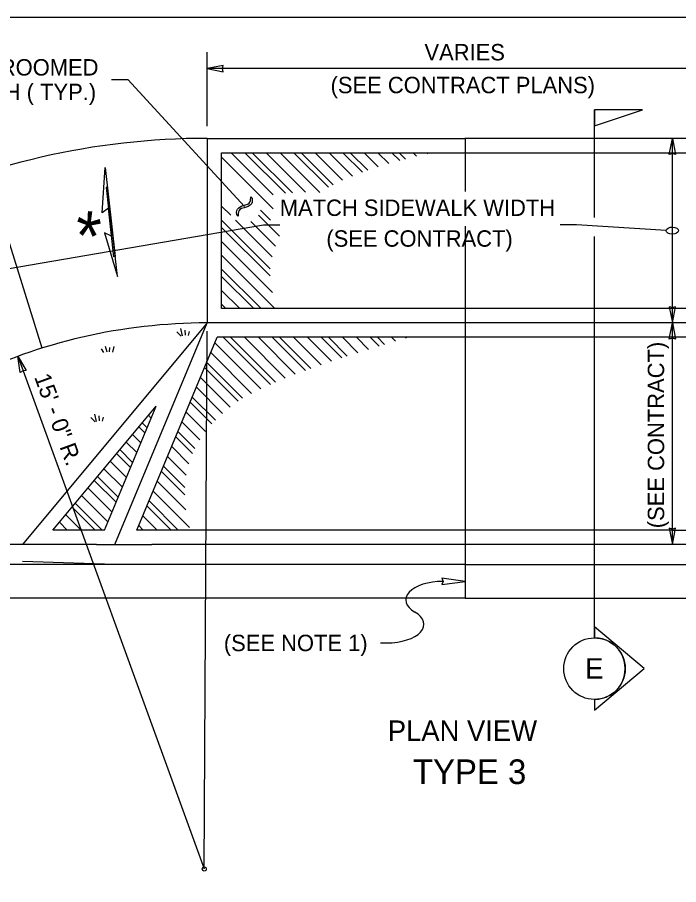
# Model space of a CAD drawing. Extents: x 99862 to 103151, y 100000 to 105076.
# Drawn here: x 100381 to 101026, y 104230 to 105076 of the extents above; entities that cross this region are included whole.
import ezdxf

# ---------------------------------------------------------------- set-up
doc = ezdxf.new("R2010")
doc.units = 0
for name, color, linetype in [('Level 1', 7, 'Continuous'), ('Level 15', 7, 'Continuous'), ('Level 18', 7, 'Continuous'), ('Level 20', 7, 'Continuous'), ('Level 48', 7, 'Continuous'), ('Level 50', 7, 'Continuous'), ('Level 57', 7, 'Continuous'), ('Level 58', 7, 'Continuous'), ('Level 7', 7, 'Continuous'), ('Level 9', 7, 'Continuous')]:
    doc.layers.add(name, color=color, linetype=linetype)

msp = doc.modelspace()

# ---------------------------------------------------------------- linework, layer by layer
at = {"layer": 'Level 1'}
msp.add_lwpolyline([(99862, 102999.5), (103151, 102999.5), (103151, 105075.5), (99862, 105075.5)], close=True, dxfattribs=at)
at = {"layer": 'Level 15'}
for p, q in [((100565.71, 104969.5), (100565.71, 105041.5)), ((100565.71, 104969.5), (100565.71, 105041.5)), ((100472.34, 105014.76), (100488.34, 105014.76)), ((100472.34, 105014.76), (100488.34, 105014.76)), ((100602.22, 104891.13), (100488.34, 105014.76)), ((100602.22, 104891.13), (100488.34, 105014.76)), ((101019.71, 104777.5), (101019.71, 104957.5)), ((100342.07, 104825.3), (100620.7, 104873.16)), ((100620.7, 104873.16), (100636.7, 104873.16)), ((100926.15, 104873.16), (100910.15, 104873.16)), ((101013.72, 104867.6), (100926.15, 104873.16)), ((101019.71, 104561.5), (101019.71, 104777.5)), ((101019.71, 104561.5), (101019.71, 104777.5)), ((100735.07, 104465.44), (100741.07, 104465.44)), ((100735.07, 104465.44), (100741.07, 104465.44))]:
    msp.add_line(p, q, dxfattribs=at)
for points in [[(100565.71, 105025.5), (100581.44, 105022.42), (100580.71, 105025.5), (100581.44, 105028.59)], [(100565.71, 105025.5), (100581.44, 105022.42), (100580.71, 105025.5), (100581.44, 105028.59)], [(101019.71, 104957.5), (101022.8, 104941.78), (101019.71, 104942.51), (101016.63, 104941.78)], [(101019.71, 104957.5), (101022.8, 104941.78), (101019.71, 104942.51), (101016.63, 104941.78)], [(101019.71, 104777.5), (101022.8, 104793.23), (101019.71, 104792.5), (101016.63, 104793.23)], [(101019.71, 104777.5), (101022.8, 104793.23), (101019.71, 104792.5), (101016.63, 104793.23)], [(101019.71, 104777.5), (101022.8, 104761.78), (101019.71, 104762.51), (101016.63, 104761.78)], [(101019.71, 104777.5), (101022.8, 104761.78), (101019.71, 104762.51), (101016.63, 104761.78)], [(100381.04, 104744.94), (100389.32, 104731.22), (100386.17, 104730.85), (100383.52, 104729.11)], [(100381.04, 104744.94), (100389.32, 104731.22), (100386.17, 104730.85), (100383.52, 104729.11)], [(101019.71, 104561.5), (101022.8, 104577.23), (101019.71, 104576.5), (101016.63, 104577.23)], [(101019.71, 104561.5), (101022.8, 104577.23), (101019.71, 104576.5), (101016.63, 104577.23)], [(100817.72, 104525.5), (100794.89, 104528.49), (100795.95, 104525.5), (100794.89, 104522.51)], [(100817.72, 104525.5), (100794.89, 104528.49), (100795.95, 104525.5), (100794.89, 104522.51)]]:
    msp.add_lwpolyline(points, close=True, dxfattribs=at)
msp.add_lwpolyline([(101069.71, 105025.5), (100565.71, 105025.5)], dxfattribs=at)
msp.add_lwpolyline([(101069.71, 105025.5), (100565.71, 105025.5)], dxfattribs=at)
msp.add_circle((100562.98, 104245.01), 2, dxfattribs=at)
msp.add_circle((100562.98, 104245.01), 2, dxfattribs=at)
msp.add_ellipse((101019.71, 104867.5), major_axis=(-6, 0.1), ratio=0.57735, dxfattribs=at)
msp.add_ellipse((101019.71, 104867.5), major_axis=(-6, 0.1), ratio=0.57735, dxfattribs=at)
for centre, start_param, end_param in [((100795.95, 104507.35), 4.712389, 6.99691), ((100795.95, 104507.35), 4.712389, 6.99691), ((100741.07, 104483.59), 1.570796, 3.855317), ((100741.07, 104483.59), 1.570796, 3.855317)]:
    msp.add_ellipse(centre, major_axis=(-36.3, 0), ratio=0.5, start_param=start_param, end_param=end_param, dxfattribs=at)
at = {"layer": 'Level 18'}
for p, q in [((100540.36, 104764.54), (100536.09, 104768.8)), ((100540.36, 104764.54), (100536.09, 104768.8)), ((100541.78, 104764.89), (100540, 104772)), ((100541.78, 104764.89), (100540, 104772)), ((100544.62, 104765.6), (100544.27, 104770.58)), ((100544.62, 104765.6), (100544.27, 104770.58)), ((100547.46, 104765.25), (100548.53, 104769.16)), ((100547.46, 104765.25), (100548.53, 104769.16)), ((100462.38, 104752.2), (100464.76, 104748.64)), ((100462.38, 104752.2), (100464.76, 104748.64)), ((100466.34, 104754.98), (100467.93, 104749.43)), ((100466.34, 104754.98), (100467.93, 104749.43)), ((100470.7, 104753.39), (100470.3, 104749.43)), ((100470.7, 104753.39), (100470.3, 104749.43)), ((100474.65, 104754.58), (100473.47, 104749.04)), ((100474.65, 104754.58), (100473.47, 104749.04)), ((100457.9, 104681.32), (100456.12, 104688.43)), ((100457.9, 104681.32), (100456.12, 104688.43)), ((100456.47, 104680.96), (100452.21, 104685.23)), ((100456.47, 104680.96), (100452.21, 104685.23)), ((100460.74, 104682.03), (100460.38, 104687.01)), ((100460.74, 104682.03), (100460.38, 104687.01)), ((100463.58, 104681.67), (100464.65, 104685.58)), ((100463.58, 104681.67), (100464.65, 104685.58))]:
    msp.add_line(p, q, dxfattribs=at)
at = {"layer": 'Level 20'}
for p, q in [((100608.14, 104896.88), (100608.33, 104900.58)), ((100608.14, 104896.88), (100608.33, 104900.58)), ((100608.33, 104900.58), (100609.76, 104899.01)), ((100608.33, 104900.58), (100609.76, 104899.01)), ((100596.64, 104889.9), (100598.94, 104891.36)), ((100596.64, 104889.9), (100598.94, 104891.36)), ((100598.94, 104891.36), (100603.15, 104892.66)), ((100598.94, 104891.36), (100603.15, 104892.66)), ((100603.15, 104892.66), (100605.47, 104893.38)), ((100603.15, 104892.66), (100605.47, 104893.38)), ((100605.47, 104893.38), (100606.72, 104894.2)), ((100605.47, 104893.38), (100606.72, 104894.2)), ((100607.85, 104892.37), (100605.8, 104891)), ((100607.85, 104892.37), (100605.8, 104891)), ((100606.72, 104894.2), (100607.59, 104895.33)), ((100606.72, 104894.2), (100607.59, 104895.33)), ((100607.59, 104895.33), (100608.14, 104896.88)), ((100607.59, 104895.33), (100608.14, 104896.88)), ((100608.93, 104893.63), (100607.85, 104892.37)), ((100608.93, 104893.63), (100607.85, 104892.37)), ((100609.59, 104895.11), (100608.93, 104893.63)), ((100609.59, 104895.11), (100608.93, 104893.63)), ((100609.86, 104896.87), (100609.59, 104895.11)), ((100609.86, 104896.87), (100609.59, 104895.11)), ((100609.76, 104899.01), (100609.86, 104896.87)), ((100609.76, 104899.01), (100609.86, 104896.87)), ((100594.55, 104885.23), (100594.8, 104887)), ((100594.55, 104885.23), (100594.8, 104887)), ((100594.72, 104883.24), (100594.55, 104885.23)), ((100594.72, 104883.24), (100594.55, 104885.23)), ((100596.14, 104881.68), (100594.72, 104883.24)), ((100596.14, 104881.68), (100594.72, 104883.24)), ((100594.8, 104887), (100595.5, 104888.55)), ((100594.8, 104887), (100595.5, 104888.55)), ((100595.5, 104888.55), (100596.64, 104889.9)), ((100595.5, 104888.55), (100596.64, 104889.9)), ((100596.4, 104885.82), (100596.14, 104884.11)), ((100596.4, 104885.82), (100596.14, 104884.11)), ((100596.14, 104884.11), (100596.15, 104881.68)), ((100596.14, 104884.11), (100596.15, 104881.68)), ((100596.95, 104887.07), (100596.4, 104885.82)), ((100596.95, 104887.07), (100596.4, 104885.82)), ((100597.8, 104888.1), (100596.95, 104887.07)), ((100597.8, 104888.1), (100596.95, 104887.07)), ((100599.43, 104889.1), (100597.8, 104888.1)), ((100599.43, 104889.1), (100597.8, 104888.1)), ((100601.87, 104889.87), (100599.43, 104889.1)), ((100601.87, 104889.87), (100599.43, 104889.1)), ((100605.8, 104891), (100601.87, 104889.87)), ((100605.8, 104891), (100601.87, 104889.87))]:
    msp.add_line(p, q, dxfattribs=at)
for points in [[(100474.84, 104842.11), (100469.46, 104889.29), (100463.45, 104884.85), (100466.16, 104929.19), (100476.07, 104842.25)], [(100467.25, 104909.43), (100472.62, 104862.25), (100465.76, 104865.23), (100478.38, 104822.64), (100468.48, 104909.57)], [(100467.25, 104909.43), (100472.62, 104862.25), (100465.76, 104865.23), (100478.38, 104822.64), (100468.48, 104909.57)], [(100467.25, 104909.43), (100472.62, 104862.25), (100465.76, 104865.23), (100478.38, 104822.64), (100468.48, 104909.57)], [(100467.25, 104909.43), (100472.62, 104862.25), (100465.76, 104865.23), (100478.38, 104822.64), (100468.48, 104909.57)]]:
    msp.add_lwpolyline(points, close=True, dxfattribs=at)
at = {"layer": 'Level 48'}
for p, q in [((100579.94, 104943.5), (101055.71, 104943.5)), ((100579.94, 104791.5), (100579.94, 104943.5)), ((100579.94, 104943.5), (101055.71, 104943.5)), ((100579.94, 104791.5), (100579.94, 104943.5)), ((101055.71, 104791.5), (100579.94, 104791.5)), ((101055.71, 104791.5), (100579.94, 104791.5)), ((100497.28, 104575.5), (100575.61, 104763.5)), ((100497.28, 104575.5), (100575.61, 104763.5)), ((101059.94, 104763.5), (100575.61, 104763.5)), ((101059.94, 104763.5), (100575.61, 104763.5)), ((100415.28, 104575.5), (100516.03, 104696.4)), ((100415.28, 104575.5), (100516.03, 104696.4)), ((100465.66, 104575.5), (100516.03, 104696.4)), ((100465.66, 104575.5), (100516.03, 104696.4)), ((100465.66, 104575.5), (100415.28, 104575.5)), ((100465.66, 104575.5), (100415.28, 104575.5)), ((101020.48, 104575.5), (100497.28, 104575.5)), ((101020.48, 104575.5), (100497.28, 104575.5)), ((101020.48, 104575.5), (101138.27, 104575.5)), ((101020.48, 104575.5), (101138.27, 104575.5))]:
    msp.add_line(p, q, dxfattribs=at)
at = {"layer": 'Level 50'}
for p, q in [((100589.11, 104943.5), (100630.08, 104902.53)), ((100602.69, 104943.5), (100642.15, 104904.04)), ((100609.76, 104943.5), (100649.01, 104904.25)), ((100623.34, 104943.5), (100661.86, 104904.98)), ((100636.91, 104943.5), (100675.61, 104904.8)), ((100650.49, 104943.5), (100684.21, 104909.78)), ((100650.49, 104943.5), (100684.21, 104909.78)), ((100657.56, 104943.5), (100688.84, 104912.22)), ((100657.56, 104943.5), (100688.84, 104912.22)), ((100671.14, 104943.5), (100698.02, 104916.62)), ((100671.14, 104943.5), (100698.02, 104916.62)), ((100684.71, 104943.5), (100707.52, 104920.7)), ((100684.71, 104943.5), (100707.52, 104920.7)), ((100698.29, 104943.5), (100717.31, 104924.48)), ((100698.29, 104943.5), (100717.31, 104924.48)), ((100705.36, 104943.5), (100722.51, 104926.35)), ((100705.36, 104943.5), (100722.51, 104926.35)), ((100718.94, 104943.5), (100732.69, 104929.75)), ((100718.94, 104943.5), (100732.69, 104929.75)), ((100732.51, 104943.5), (100743.1, 104932.92)), ((100732.51, 104943.5), (100743.1, 104932.92)), ((100746.09, 104943.5), (100753.71, 104935.88)), ((100746.09, 104943.5), (100753.71, 104935.88)), ((100753.16, 104943.5), (100759.31, 104937.35)), ((100753.16, 104943.5), (100759.31, 104937.35)), ((100766.74, 104943.5), (100770.21, 104940.03)), ((100766.74, 104943.5), (100770.21, 104940.03)), ((100780.31, 104943.5), (100781.27, 104942.55)), ((100780.31, 104943.5), (100781.27, 104942.55)), ((100579.94, 104939.09), (100630.13, 104888.91)), ((100579.94, 104891.29), (100588.77, 104882.47)), ((100579.94, 104891.29), (100588.77, 104882.47)), ((100615.77, 104882.62), (100636.42, 104861.97)), ((100615.77, 104882.62), (100636.42, 104861.97)), ((100617.83, 104887.63), (100627.62, 104877.84)), ((100579.94, 104877.72), (100627.39, 104830.27)), ((100579.94, 104877.72), (100627.39, 104830.27)), ((100593.55, 104877.68), (100629.22, 104842.02)), ((100593.55, 104877.68), (100629.22, 104842.02)), ((100608.43, 104876.39), (100632.37, 104852.44)), ((100608.43, 104876.39), (100632.37, 104852.44)), ((100579.94, 104870.65), (100627.23, 104823.36)), ((100579.94, 104870.65), (100627.23, 104823.36)), ((100579.94, 104857.07), (100629.7, 104807.31)), ((100579.94, 104857.07), (100629.7, 104807.31)), ((100579.94, 104843.49), (100631.93, 104791.5)), ((100579.94, 104843.49), (100631.93, 104791.5)), ((100579.94, 104829.92), (100618.36, 104791.5)), ((100579.94, 104829.92), (100618.36, 104791.5)), ((100579.94, 104822.85), (100611.29, 104791.5)), ((100579.94, 104822.85), (100611.29, 104791.5)), ((100579.94, 104809.27), (100597.71, 104791.5)), ((100579.94, 104809.27), (100597.71, 104791.5)), ((100579.94, 104795.69), (100584.13, 104791.5)), ((100579.94, 104795.69), (100584.13, 104791.5)), ((100573.38, 104758.13), (100618.15, 104713.36)), ((100573.38, 104758.13), (100618.15, 104713.36)), ((100581.59, 104763.5), (100627.48, 104717.6)), ((100581.59, 104763.5), (100627.48, 104717.6)), ((100588.66, 104763.5), (100632.43, 104719.73)), ((100588.66, 104763.5), (100632.43, 104719.73)), ((100602.23, 104763.5), (100642.05, 104723.69)), ((100602.23, 104763.5), (100642.05, 104723.69)), ((100615.81, 104763.5), (100651.81, 104727.5)), ((100615.81, 104763.5), (100651.81, 104727.5)), ((100629.39, 104763.5), (100661.7, 104731.19)), ((100629.39, 104763.5), (100661.7, 104731.19)), ((100636.46, 104763.5), (100666.89, 104733.07)), ((100636.46, 104763.5), (100666.89, 104733.07)), ((100650.03, 104763.5), (100676.92, 104736.61)), ((100650.03, 104763.5), (100676.92, 104736.61)), ((100663.61, 104763.5), (100687.04, 104740.07)), ((100663.61, 104763.5), (100687.04, 104740.07)), ((100677.19, 104763.5), (100697.23, 104743.46)), ((100677.19, 104763.5), (100697.23, 104743.46)), ((100684.26, 104763.5), (100702.56, 104745.2)), ((100684.26, 104763.5), (100702.56, 104745.2)), ((100697.83, 104763.5), (100712.84, 104748.49)), ((100697.83, 104763.5), (100712.84, 104748.49)), ((100711.41, 104763.5), (100723.18, 104751.73)), ((100711.41, 104763.5), (100723.18, 104751.73)), ((100724.99, 104763.5), (100733.57, 104754.92)), ((100724.99, 104763.5), (100733.57, 104754.92)), ((100732.06, 104763.5), (100739, 104756.56)), ((100732.06, 104763.5), (100739, 104756.56)), ((100745.63, 104763.5), (100749.46, 104759.68)), ((100745.63, 104763.5), (100749.46, 104759.68)), ((100759.21, 104763.5), (100759.95, 104762.76)), ((100759.21, 104763.5), (100759.95, 104762.76)), ((100569.38, 104748.55), (100609.08, 104708.85)), ((100569.38, 104748.55), (100609.08, 104708.85)), ((100565.39, 104738.97), (100600.38, 104703.98)), ((100565.39, 104738.97), (100600.38, 104703.98)), ((100563.31, 104733.98), (100596.04, 104701.24)), ((100563.31, 104733.98), (100596.04, 104701.24)), ((100559.32, 104724.39), (100588.22, 104695.49)), ((100559.32, 104724.39), (100588.22, 104695.49)), ((100555.32, 104714.81), (100580.83, 104689.3)), ((100555.32, 104714.81), (100580.83, 104689.3)), ((100551.33, 104705.23), (100573.89, 104682.67)), ((100551.33, 104705.23), (100573.89, 104682.67)), ((100549.25, 104700.23), (100570.46, 104679.03)), ((100549.25, 104700.23), (100570.46, 104679.03)), ((100514.72, 104694.82), (100515.18, 104694.36)), ((100514.72, 104694.82), (100515.18, 104694.36)), ((100545.26, 104690.65), (100564.28, 104671.63)), ((100545.26, 104690.65), (100564.28, 104671.63)), ((100502.37, 104680.01), (100507.19, 104675.19)), ((100502.37, 104680.01), (100507.19, 104675.19)), ((100508.54, 104687.41), (100511.19, 104684.77)), ((100508.54, 104687.41), (100511.19, 104684.77)), ((100541.27, 104681.07), (100558.7, 104663.63)), ((100541.27, 104681.07), (100558.7, 104663.63)), ((100499.16, 104676.15), (100505.11, 104670.2)), ((100499.16, 104676.15), (100505.11, 104670.2)), ((100537.27, 104671.48), (100553.81, 104654.95)), ((100537.27, 104671.48), (100553.81, 104654.95)), ((100492.99, 104668.75), (100501.12, 104660.61)), ((100492.99, 104668.75), (100501.12, 104660.61)), ((100535.19, 104666.49), (100551.57, 104650.12)), ((100535.19, 104666.49), (100551.57, 104650.12)), ((100486.82, 104661.34), (100497.13, 104651.03)), ((100486.82, 104661.34), (100497.13, 104651.03)), ((100531.2, 104656.91), (100547.96, 104640.15)), ((100531.2, 104656.91), (100547.96, 104640.15)), ((100477.43, 104650.08), (100491.05, 104636.46)), ((100477.43, 104650.08), (100491.05, 104636.46)), ((100480.65, 104653.94), (100493.13, 104641.45)), ((100480.65, 104653.94), (100493.13, 104641.45)), ((100527.21, 104647.33), (100545.39, 104629.14)), ((100527.21, 104647.33), (100545.39, 104629.14)), ((100471.26, 104642.67), (100487.06, 104626.87)), ((100471.26, 104642.67), (100487.06, 104626.87)), ((100523.21, 104637.74), (100544.07, 104616.89)), ((100523.21, 104637.74), (100544.07, 104616.89)), ((100465.09, 104635.27), (100483.07, 104617.29)), ((100465.09, 104635.27), (100483.07, 104617.29)), ((100521.13, 104632.75), (100543.96, 104609.92)), ((100521.13, 104632.75), (100543.96, 104609.92)), ((100455.7, 104624.01), (100476.99, 104602.72)), ((100455.7, 104624.01), (100476.99, 104602.72)), ((100458.92, 104627.86), (100479.07, 104607.71)), ((100458.92, 104627.86), (100479.07, 104607.71)), ((100517.14, 104623.17), (100545.14, 104595.17)), ((100517.14, 104623.17), (100545.14, 104595.17)), ((100449.53, 104616.6), (100473, 104593.13)), ((100449.53, 104616.6), (100473, 104593.13)), ((100513.15, 104613.59), (100548.63, 104578.1)), ((100513.15, 104613.59), (100548.63, 104578.1)), ((100443.36, 104609.2), (100469.01, 104583.55)), ((100443.36, 104609.2), (100469.01, 104583.55)), ((100509.15, 104604), (100537.65, 104575.5)), ((100509.15, 104604), (100537.65, 104575.5)), ((100433.98, 104597.93), (100456.41, 104575.5)), ((100433.98, 104597.93), (100456.41, 104575.5)), ((100437.19, 104601.79), (100463.48, 104575.5)), ((100437.19, 104601.79), (100463.48, 104575.5)), ((100507.07, 104599.01), (100530.58, 104575.5)), ((100507.07, 104599.01), (100530.58, 104575.5)), ((100427.8, 104590.53), (100442.83, 104575.5)), ((100427.8, 104590.53), (100442.83, 104575.5)), ((100503.08, 104589.43), (100517.01, 104575.5)), ((100503.08, 104589.43), (100517.01, 104575.5)), ((100421.63, 104583.12), (100429.26, 104575.5)), ((100421.63, 104583.12), (100429.26, 104575.5)), ((100499.09, 104579.84), (100503.43, 104575.5)), ((100499.09, 104579.84), (100503.43, 104575.5)), ((100415.46, 104575.72), (100415.68, 104575.5)), ((100415.46, 104575.72), (100415.68, 104575.5)), ((100457.72, 104561.5), (100511.72, 104561.5)), ((100457.72, 104561.5), (100511.72, 104561.5))]:
    msp.add_line(p, q, dxfattribs=at)
at = {"layer": 'Level 57'}
for p, q in [((100817.71, 104957.94), (100817.71, 104943.27)), ((100817.71, 104957.94), (100817.71, 104905.83)), ((101069.72, 104957.5), (100817.71, 104957.5)), ((101069.72, 104957.5), (100817.71, 104957.5)), ((100404.84, 104752.98), (100351.22, 104924.81)), ((100817.71, 104871.87), (100817.72, 104509)), ((100565.72, 104777.5), (100385.71, 104561.5)), ((100565.72, 104777.5), (100385.71, 104561.5)), ((100457.72, 104561.5), (99893.41, 104561.5)), ((100817.71, 104561.5), (100511.72, 104561.5)), ((100817.71, 104561.5), (100511.72, 104561.5)), ((101123.71, 104561.5), (100817.72, 104561.5)), ((101123.71, 104561.5), (100817.72, 104561.5)), ((100475.71, 104542), (100385.71, 104545)), ((100475.71, 104542), (100385.71, 104545)), ((100457.72, 104542), (99893.41, 104542)), ((100511.72, 104542), (100457.72, 104542)), ((100511.72, 104542), (100457.72, 104542)), ((100817.71, 104542), (100511.72, 104542)), ((100817.71, 104542), (100511.72, 104542)), ((100817.72, 104542), (101123.71, 104542)), ((100817.72, 104542), (101123.71, 104542)), ((100457.72, 104509), (99893.41, 104509)), ((100511.72, 104509), (100457.72, 104509)), ((100511.72, 104509), (100457.72, 104509)), ((100817.71, 104509), (100511.72, 104509)), ((100817.71, 104509), (100511.72, 104509)), ((100817.72, 104509), (101123.71, 104509)), ((100817.72, 104509), (101123.71, 104509))]:
    msp.add_line(p, q, dxfattribs=at)
msp.add_lwpolyline([(100565.71, 104957.5), (100817.71, 104957.5)], dxfattribs=at)
msp.add_lwpolyline([(100565.71, 104957.5), (100817.71, 104957.5)], dxfattribs=at)
for centre, radius, end in [((100565.71, 104237.5), 720, 115.99798), ((100565.71, 104237.5), 540, 115.99798), ((100565.71, 104237.5), 540, 115.99798), ((100565.72, 104237.5), 540, 90.00003), ((100565.72, 104237.5), 540, 90.00003)]:
    msp.add_arc(centre, radius, 90, end, dxfattribs=at)
at = {"layer": 'Level 58'}
for p, q in [((100565.71, 104957.5), (100565.71, 104777.5)), ((100565.71, 104957.5), (100565.71, 104777.5)), ((101069.71, 104777.5), (100817.71, 104777.5))]:
    msp.add_line(p, q, dxfattribs=at)
for points in [[(100475.71, 104561.5), (100565.72, 104777.5)], [(100475.71, 104561.5), (100565.72, 104777.5)], [(100817.72, 104777.5), (100565.72, 104777.5)], [(100817.72, 104777.5), (100565.72, 104777.5)]]:
    msp.add_lwpolyline(points, dxfattribs=at)
at = {"layer": 'Level 7'}
for p, q in [((100562.98, 104245.01), (100565.72, 104769.5)), ((100562.98, 104245.01), (100565.72, 104769.5)), ((100381.04, 104744.94), (100562.98, 104245.01)), ((100381.04, 104744.94), (100562.98, 104245.01))]:
    msp.add_line(p, q, dxfattribs=at)
at = {"layer": 'Level 9'}
for p, q in [((100943.71, 104880.29), (100943.71, 104985.28)), ((100943.71, 104601.26), (100943.71, 104861.72)), ((100943.71, 104470.4), (100943.71, 104601.26)), ((100943.71, 104470.4), (100943.71, 104601.26)), ((100943.71, 104481), (100943.71, 104470.4)), ((100992.18, 104440.4), (100943.71, 104481)), ((100943.71, 104399.8), (100992.18, 104440.4)), ((100943.71, 104410.4), (100943.71, 104399.8))]:
    msp.add_line(p, q, dxfattribs=at)
msp.add_lwpolyline([(100943.71, 104969.75), (100990.59, 104985.28), (100943.71, 104985.28)], close=True, dxfattribs=at)
msp.add_lwpolyline([(100943.71, 104969.75), (100990.59, 104985.28), (100943.71, 104985.28)], close=True, dxfattribs=at)
msp.add_circle((100943.71, 104440.4), 30, dxfattribs=at)
msp.add_arc((100943.71, 104440.4), 30, 269.99779, 90.00221, dxfattribs=at)

# ---------------------------------------------------------------- texts
at = {"layer": 'Level 20'}
for s, height, p in [('VARIES', 16, (100777.86, 105033.5)), ('BROOMED', 16, (100349.25, 105018.76)), ('(SEE CONTRACT PLANS)', 16, (100686.26, 105001.5)), ('FINISH ( TYP.)', 16, (100313.66, 104994.76)), ('MATCH SIDEWALK WIDTH', 16, (100636.7, 104881.83)), ('(SEE CONTRACT)', 16, (100682.12, 104851.83)), ('(SEE NOTE 1)', 16, (100582.1, 104457.44)), ('E', 20, (100934.68, 104430.59)), ('PLAN VIEW', 20, (100742.06, 104369.85)), (' TYPE 3', 24, (100757.71, 104327.85))]:
    msp.add_text(s, height=height, dxfattribs=at).set_placement(p)
for s, height, rotation, p in [('*', 48, 354.80672, (100434.76, 104839.69)), ('(SEE CONTRACT)', 16, 90, (101011.71, 104577.29)), ('15\' - 0" R.', 16, 289.99824, (100396.88, 104724.83))]:
    msp.add_text(s, height=height, rotation=rotation, dxfattribs=at).set_placement(p)

doc.saveas('drawing.dxf')
